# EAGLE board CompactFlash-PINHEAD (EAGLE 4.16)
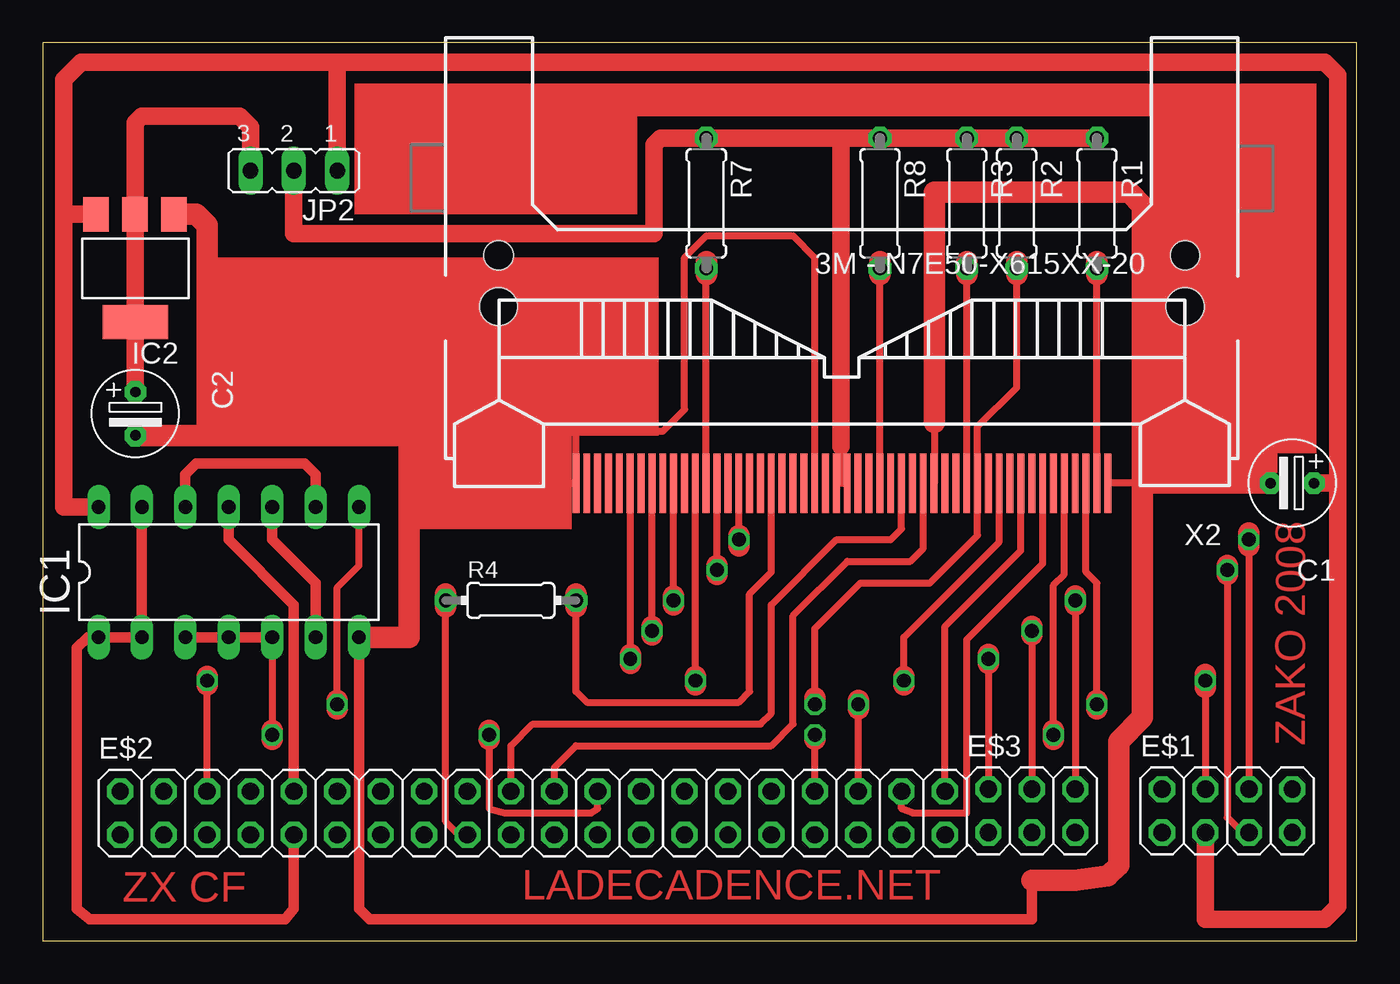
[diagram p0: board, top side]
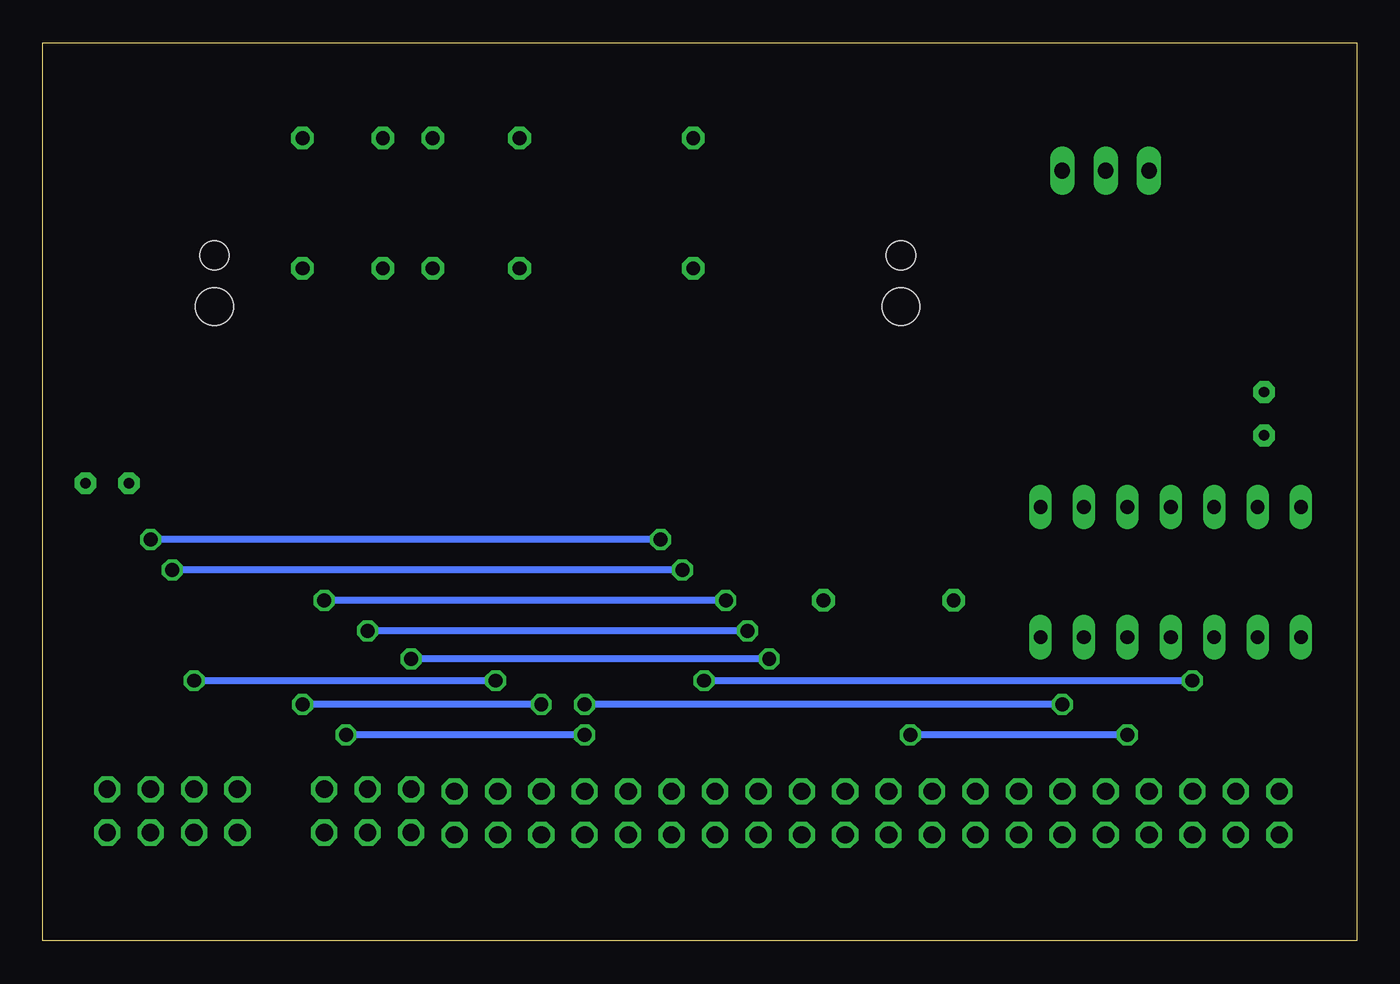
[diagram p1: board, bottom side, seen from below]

Size 76.89 x 52.57 mm. Coordinates in mm from the lower left corner, seen from the top.
Outline: 0,0 76.89,0 76.89,52.57 0,52.57 0,0
Copper layers (1*16): Top 0.035mm / dielectric 1.5mm / Bottom 0.035mm
Design rules "default": minimum track width 10mil, minimum drill 24mil, track to track 8mil, track to pad 8mil, pad to pad 8mil, via to via 8mil, smd to smd 8mil, copper to edge 40mil, drill to drill 8mil, minimum pad ring 10mil, minimum via ring 8mil, stop-mask expansion 4mil, vias tented up to drill 0mil, thermal gap 10mil

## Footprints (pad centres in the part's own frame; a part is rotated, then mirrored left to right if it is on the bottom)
ES-2,5L = drill 0.61 pad 1.27 octagon: 1 0,0; 2 2.54,0
2X04 = drill 1.016 octagon: 1 -3.81,-1.27; 2 -3.81,1.27; 3 -1.27,-1.27; 4 -1.27,1.27; 5 1.27,-1.27; 6 1.27,1.27; 7 3.81,-1.27; 8 3.81,1.27
2X20 = drill 1.016 octagon: 1 -24.13,-1.27; 2 -24.13,1.27; 3 -21.59,-1.27; 4 -21.59,1.27; 5 -19.05,-1.27; 6 -19.05,1.27; 7 -16.51,-1.27; 8 -16.51,1.27; 9 -13.97,-1.27; 10 -13.97,1.27; 11 -11.43,-1.27; 12 -11.43,1.27; 13 -8.89,-1.27; 14 -8.89,1.27; 15 -6.35,-1.27; 16 -6.35,1.27; 17 -3.81,-1.27; 18 -3.81,1.27; 19 -1.27,-1.27; 20 -1.27,1.27; 21 1.27,-1.27; 22 1.27,1.27; 23 3.81,-1.27; 24 3.81,1.27; 25 6.35,-1.27; 26 6.35,1.27; 27 8.89,-1.27; 28 8.89,1.27; 29 11.43,-1.27; 30 11.43,1.27; 31 13.97,-1.27; 32 13.97,1.27; 33 16.51,-1.27; 34 16.51,1.27; 35 19.05,-1.27; 36 19.05,1.27; 37 21.59,-1.27; 38 21.59,1.27; 39 24.13,-1.27; 40 24.13,1.27
2X03 = drill 1.016 octagon: 1 -2.54,-1.27; 2 -2.54,1.27; 3 0,-1.27; 4 0,1.27; 5 2.54,-1.27; 6 2.54,1.27
DIL14 = drill 0.8 long: 1 -7.62,-3.81; 2 -5.08,-3.81; 3 -2.54,-3.81; 4 0,-3.81; 5 2.54,-3.81; 6 5.08,-3.81; 7 7.62,-3.81; 8 7.62,3.81; 9 5.08,3.81; 10 2.54,3.81; 11 0,3.81; 12 -2.54,3.81; 13 -5.08,3.81; 14 -7.62,3.81
SOT223 = smd 1.499 x 2.007: 1 -2.261,-3.15; 2 0.025,-3.15; 3 2.311,-3.15 | smd 3.81 x 2.007: 4 0,3.15
JP2 = drill 0.914 long: 1 -2.54,0; 2 0,0; 3 2.54,0
0207/7 = drill 0.813 octagon: 1 -3.81,0; 2 3.81,0
0204/7 = drill 0.813 octagon: 1 -3.81,0; 2 3.81,0
N7E50615 = smd 0.4 x 3.5: 1 -15.557,10.335; 2 -14.287,10.335; 3 -13.018,10.335; 4 -11.748,10.335; 5 -10.477,10.335; 6 -9.207,10.335; 7 -7.938,10.335; 8 -6.668,10.335; 9 -5.397,10.335; 10 -4.128,10.335; 11 -2.857,10.335; 12 -1.587,10.335; 13 -0.318,10.335; 14 0.953,10.335; 15 2.223,10.335; 16 3.493,10.335; 17 4.763,10.335; 18 6.032,10.335; 19 7.303,10.335; 20 8.572,10.335; 21 9.842,10.335; 22 11.113,10.335; 23 12.383,10.335; 24 13.652,10.335; 25 14.922,10.335; 26 -14.922,10.335; 27 -13.652,10.335; 28 -12.383,10.335; 29 -11.113,10.335; 30 -9.842,10.335; 31 -8.572,10.335; 32 -7.303,10.335; 33 -6.032,10.335; 34 -4.763,10.335; 35 -3.493,10.335; 36 -2.223,10.335; 37 -0.953,10.335; 38 0.318,10.335; 39 1.587,10.335; 40 2.857,10.335; 41 4.128,10.335; 42 5.397,10.335; 43 6.668,10.335; 44 7.938,10.335; 45 9.207,10.335; 46 10.477,10.335; 47 11.748,10.335; 48 13.018,10.335; 49 14.287,10.335; 50 15.557,10.335 | hole 1.7: -20.08,-3; 20.08,-3 | hole 2.2: -20.08,0; 20.08,0

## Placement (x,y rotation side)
C1  10uF  [ES-2,5L]  74.38,26.79 180 top
C2  10u  [ES-2,5L]  5.42,32.13 270 top
E$1  [2X04]  69.3,7.62 0 top
E$2  [2X20]  28.66,7.49 0 top
E$3  [2X03]  57.87,7.62 0 top
IC1  74HC10N  [DIL14]  10.88,21.58 0 top
IC2  REG1117  [SOT223]  5.42,39.37 180 top
JP2  [JP2]  14.69,45.08 180 top
R1  10k  [0207/7]  61.68,43.18 270 top
R2  10k  [0207/7]  56.98,43.18 270 top
R3  10k  [0207/7]  54.06,43.18 270 top
R4  10k  [0204/7]  27.39,19.93 0 top
R7  10k  [0207/7]  38.82,43.18 270 top
R8  10k  [0207/7]  48.98,43.18 270 top
X2  N7E50615  [N7E50615]  46.75,37.13 180 top

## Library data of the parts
C1 C2 = discrete
E$1-E$3 = pinhead
IC1 = 74xx-eu
IC2 = burr-brown
JP2 = jumper
R1-R4 R7 R8 = rcl
X2 = con-3m

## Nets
36: R8.2 X2.36
44: R7.2 X2.44
/CD1: R1.2 X2.26
/CS0: IC1.8 R2.2 X2.7
/CS1: R3.2 X2.32
/IORD: X2.34
/IORQ: IC1.3 IC1.4 IC1.5
/IOWR: X2.35
/RESET: R4.2 X2.41
A0: X2.20
A1: X2.19
A2: X2.18
A4: IC1.1 IC1.2 IC1.13
D0: X2.21
D1: X2.22
D2: X2.23
D3: X2.2
D4: X2.3
D5: X2.4
D6: X2.5
D7: X2.6
GND: C1.2 C2.2 IC1.7 IC2.1 X2.1 X2.9 X2.39 X2.50
N$1: JP2.2 R1.1 R2.1 R3.1 R7.1 R8.1 X2.13 X2.38
N$3: R4.1
N$6: IC1.9 IC1.12
N$7: C2.1 IC2.2 JP2.3
N$13: IC1.6 IC1.10
N$16: IC1.11
VCC: C1.1 IC1.14 IC2.3 JP2.1

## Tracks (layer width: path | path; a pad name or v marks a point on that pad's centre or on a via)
36
  Top 0.406: X2.36 48.98,26.87 48.98,38.98 R8.2
  Top 1.27: 48.98,39.75 R8.2 48.98,38.98
44
  Top 0.406: X2.44 R7.2
  Top 1.27: 38.82,39.75 R7.2 38.82,38.98
/CD1
  Top 0.406: X2.26 61.68,26.87 61.68,38.98 R1.2
  Top 1.27: 61.68,39.75 R1.2 61.68,38.98
/CS0  (via drill 0.81)
  Top 0.406: 56.98,38.98 56.98,32.38 54.7,30.09 54.7,26.87 X2.7 54.7,23.74 51.91,20.95 47.84,20.95 45.17,18.28 45.17,14.22 | IC1.8 18.5,21.97 17.23,20.7 17.23,14.09
  Top 1.27: v17.23,13.84 17.23,14.09 17.23,13.58 | 56.98,39.75 R2.2 56.98,38.98 | v45.17,13.84 45.17,14.22
  Bottom 0.406: v17.23,13.84 v45.17,13.84
/CS1
  Top 0.406: X2.32 54.06,26.87 54.06,38.98 R3.2
  Top 1.27: 54.06,39.75 R3.2 54.06,38.98
/IORD
  Top 0.406: X2.34 51.52,22.97 50.76,22.22 47.08,22.22 43.9,19.04 43.9,12.7 42.63,11.43 31.2,11.43 29.93,10.16 29.93,8.63
/IORQ  (via drill 0.81)
  Top 0.406: 32.47,8.63 32.47,7.74 32.09,7.49 27.01,7.49 26.12,7.74 26.12,11.81 | IC1.5 13.42,12.31
  Top 0.61: IC1.3 IC1.4 IC1.5
  Top 1.27: 26.12,12.31 v26.12,12.06 26.12,11.81 | v13.42,12.06 13.42,12.31 13.42,11.81
  Bottom 0.406: v13.42,12.06 v26.12,12.06
/IOWR
  Top 0.406: X2.35 50.25,24.12 49.62,23.49 46.44,23.49 42.63,19.68 42.63,13.33 42,12.7 28.66,12.7 27.39,11.43 27.39,8.63
/RESET
  Top 0.406: X2.41 42.63,21.58 41.36,20.31 41.36,14.6 40.73,13.97 31.84,13.97 31.2,14.6 31.2,19.55 R4.2
  Top 1.27: 31.2,20.31 R4.2 31.2,19.55
A0  (via drill 0.81)
  Top 0.406: X2.20 38.19,15.49 | 9.61,8.63 9.61,14.98
  Top 1.27: v38.19,15.24 38.19,15.49 38.19,14.98 | 9.61,15.49 v9.61,15.24 9.61,14.98
  Bottom 0.406: v9.61,15.24 v38.19,15.24
A1  (via drill 0.81)
  Top 0.406: 70.57,6.22 70.57,5.96 69.3,7.23 69.3,21.46 | X2.19 | X2.19 | 39.46,21.97 X2.19
  Top 1.27: 69.3,21.97 v69.3,21.71 69.3,21.46 | v39.46,21.71 39.46,21.97 39.46,21.46
  Bottom 0.406: v39.46,21.71 v69.3,21.71
A2  (via drill 0.81)
  Top 0.406: 70.57,23.11 70.57,8.63 | X2.18 | X2.18 | 40.73,23.74 X2.18
  Top 1.27: 70.57,23.87 v70.57,23.49 70.57,23.11 | v40.73,23.49 40.73,23.74 40.73,23.11
  Bottom 0.406: v40.73,23.49 v70.57,23.49
A4
  Top 0.61: IC1.2 IC1.13 | IC1.2 IC1.1 | 14.69,6.22 14.69,1.9 14.19,1.27 2.76,1.27 1.99,1.9 1.99,17.14 2.63,17.77 IC1.2
D0  (via drill 0.81)
  Top 0.406: 60.41,19.68 60.41,8.63 | X2.21 36.92,20.19
  Top 1.27: 60.41,20.19 v60.41,19.93 60.41,19.68 | v36.92,19.93 36.92,20.19 36.92,19.68
  Bottom 0.406: v36.92,19.93 v60.41,19.93
D1  (via drill 0.81)
  Top 0.406: 57.87,17.9 57.87,8.63 | X2.22 35.65,18.41
  Top 1.27: 57.87,18.41 v57.87,18.16 57.87,17.9 | v35.65,18.16 35.65,18.41 35.65,17.9
  Bottom 0.406: v35.65,18.16 v57.87,18.16
D2  (via drill 0.81)
  Top 0.406: 55.33,16.25 55.33,8.63 | X2.23 34.38,16.76
  Top 1.27: 55.33,16.76 v55.33,16.5 55.33,16.25 | v34.38,16.5 34.38,16.76 34.38,16.25
  Bottom 0.406: v34.38,16.5 v55.33,16.5
D3  (via drill 0.81)
  Top 0.406: X2.2 61.04,21.59 61.68,20.95 61.68,14.09 | 47.71,8.63 47.71,13.58
  Top 1.27: 47.71,14.09 v47.71,13.84 47.71,13.58 | v61.68,13.84 61.68,14.09 61.68,13.58
  Bottom 0.406: v47.71,13.84 v61.68,13.84
D4  (via drill 0.81)
  Top 0.406: X2.3 59.77,21.45 59.14,20.82 59.14,12.31 | 45.17,8.63 45.17,11.81
  Top 1.27: 59.14,11.81 v59.14,12.06 59.14,12.31 | 45.17,11.81 v45.17,12.06
  Bottom 0.406: v45.17,12.06 v59.14,12.06
D5
  Top 0.406: 50.25,8.63 50.25,7.74 50.89,7.49 54.06,7.49 54.06,17.65 58.51,22.09 X2.4
D6
  Top 0.406: X2.5 57.23,22.85 52.79,18.41 52.79,8.63
D7  (via drill 0.81)
  Top 0.406: 68.03,14.85 68.03,8.63 | X2.6 55.97,23.36 50.38,17.77 50.38,15.49
  Top 1.27: 68.03,15.62 v68.03,15.24 68.03,14.85 | v50.38,15.24 50.38,15.49 50.38,14.98
  Bottom 0.406: v50.38,15.24 v68.03,15.24
GND
  Top 0.406: X2.9 52.16,30.35 | X2.39 45.17,40.01 43.9,41.27 38.82,41.27 37.55,40 37.55,31.11 36.28,29.84 31.2,29.84 X2.50 27.52,26.79 27.39,26.79 | IC2.1 7.71,42.52 7.71,42.54 | X2.1 64.35,26.79 X2.1
  Top 0.61: IC1.7 18.5,1.9 19.14,1.27 57.87,1.27 57.87,3.55
  Top 1.27: 57.87,3.55 60.41,3.55 62.32,3.8 62.95,4.44 62.95,11.68 64.35,13.08 64.35,26.79 | 64.35,26.79 C1.2 | 64.35,26.79 64.35,43.05 63.59,43.81 52.16,43.81 52.16,30.35 | 9.61,29.59 C2.2 | 9.61,29.59 9.61,41.91 8.98,42.54 7.71,42.54 | 9.61,29.59 21.42,29.59 21.42,26.79 | 21.42,26.79 21.42,17.77 IC1.7 | 21.42,26.79 27.39,26.79 29.3,26.79
N$1
  Top 0.406: 46.7,28.95 46.7,26.79 | X2.13 | 46.7,26.79 X2.38 | 46.7,26.79 X2.13 | X2.13
  Top 1.016: R1.1 R2.1 R3.1 R8.1 46.7,46.98 | 46.7,46.98 R7.1 36.16,46.98 35.78,46.6 35.78,41.4 14.69,41.4 JP2.2 | 46.7,46.98 46.7,28.95
N$3
  Top 0.406: 24.85,5.96 24.85,5.71 23.58,6.98 23.58,19.55
  Top 1.27: 23.58,20.31 R4.1 23.58,19.55
N$6
  Top 0.61: IC1.12 8.34,27.3 8.98,27.93 15.33,27.93 15.96,27.3 IC1.9
N$7
  Top 1.016: JP2.3 12.15,47.62 11.52,48.26 5.8,48.26 5.42,47.87 5.42,42.54 | 5.42,42.54 IC2.2 | C2.1 5.42,42.54
N$13
  Top 0.61: IC1.6 15.96,20.95 13.42,23.49 IC1.10
N$16
  Top 0.61: 14.69,8.63 14.69,19.68 10.88,23.49 IC1.11
VCC
  Top 1.016: 68.03,6.34 68.03,1.27 75.02,1.27 75.78,2.03 75.78,26.79 | 75.78,26.79 C1.1 | 75.78,26.79 75.78,50.67 75.02,51.43 17.23,51.43 | IC1.14 1.23,25.39 1.23,42.54 | 3.11,42.44 3.14,42.41 | 3.11,42.44 IC2.3 | 1.23,42.54 3.01,42.54 3.11,42.44 | 17.23,51.43 JP2.1 | 17.23,51.43 2.25,51.43 1.23,50.41 1.23,42.54
(copper drawn outside any net)
  shapes: Top area x6

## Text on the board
Top: ZAKO 2008 | ZX CF | LADECADENCE.NET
